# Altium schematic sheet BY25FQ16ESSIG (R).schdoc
size 127 x 101 mm
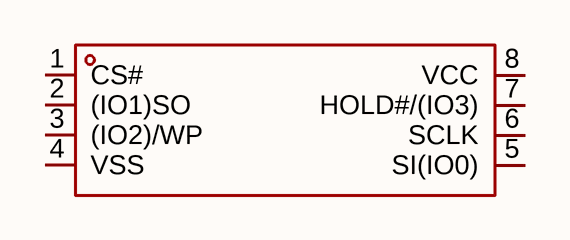
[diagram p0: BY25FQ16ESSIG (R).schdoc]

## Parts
U?  by25fq16essig (r)  [VSOP-8_L5.3-W5.3-P1.27-LS7.9-BL]  (value not drawn)

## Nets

Not connected (* = marked no-connect by the designer): U? 1(CS#) 2((IO1)SO) 3((IO2)/WP) 4(VSS) 5(SI(IO0)) 6(SCLK) 7(HOLD#/(IO3)) 8(VCC)

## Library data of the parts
U? = by25fq16essig (r): Manufacturer: BOYAMICRO(博雅); AddInBom: yes; ModelId: f5e47a51abb24d71a02f5e3265e8791a; ModelName: VSOP-8L_L5.3-W5.3-H1.0-P1.27-LS7.9-BL; ModelTransform: 207.8736,311.023,0,0,0,0,0,0,0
